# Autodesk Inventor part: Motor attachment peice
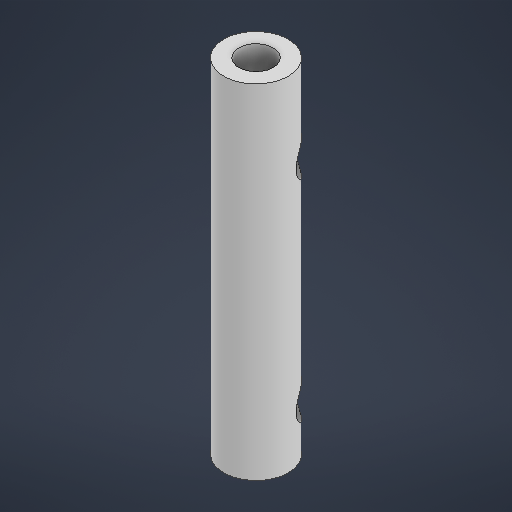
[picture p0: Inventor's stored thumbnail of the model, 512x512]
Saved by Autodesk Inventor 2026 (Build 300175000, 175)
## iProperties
Created: 2025-10
Part Number: Motor attachment peice
Material: Generic
Document SubType Name: Modeling
Designer: sab273
Density: 1 g/cm^3
Appearance: Default
Author: sab273
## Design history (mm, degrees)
sketch "Sketch1"
  geometry: C1 r 3.75 at (0, 0); 1 further point
  constraints: 1 centre point, 1 coincident
  dimensions: "d0" = 7.5 diameter of C1
extrude "Extrusion1" new body sketch "Sketch1" distance "d1" = 40; taper "d2" = 0 deg
sketch "Sketch2"
  geometry: L1 (0, -2.05)-(2.032, -0.272); A1 r 2.05 centre (0, 0) between (2.032, -0.272) and (0, -2.05); 1 further point
  constraints: 2 end point, 2 point on circle, 1 centre point, 1 coincident
extrude "Extrusion2" cut sketch "Sketch2" distance "d4" = 11; taper "d5" = 0 deg
sketch "Sketch3"
  geometry: L1 (-1.35, 0)-(-1.35, 5.5); C1 r 2 at (-1.35, 5.5)
  constraints: 2 end point, 1 centre point, 1 coincident, 1 vertical
  dimensions: "d6" = 5.5 distance of L1.start L1.end; "d7" = 4 diameter of C1
extrude "Extrusion3" cut sketch "Sketch3" distance "d8" = 1; taper "d9" = 0 deg; dims "d10" = 5.5, "d11" = 0
sketch "Sketch4"
  geometry: C1 r 2 at (0, 0); 1 further point
  constraints: 1 centre point, 1 coincident
extrude "Extrusion4" cut sketch "Sketch4" distance "d13" = 20; taper "d14" = 0 deg
workplane "Work Plane1"
sketch "Sketch5"
  geometry: L1 (3.75, 40)-(-3.75, 40) reference; C1 r 2 at (0, 30); 1 further point
  constraints: 1 centre point
extrude "Extrusion5" cut sketch "Sketch5" distance "d17" = 3.75; taper "d18" = 0 deg
body "Solid1"
